Omron CX-Programmer project NewProject (CX-Programmer 7.20)

# PLC NewPLC1: CJ1M CPU11
I/O table (CPU CJ1M-CPU11): rack 0 slot 0 CJ1W-ETN21(ETN21Mode); rack 0 slot 1 CJ1W-ID211; rack 0 slot 2 CJ1W-OC211

## Program NewProgram1 (cyclic task 0)

### Section Section1

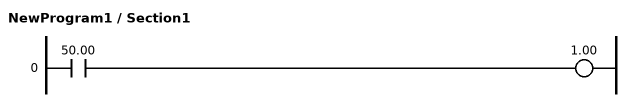
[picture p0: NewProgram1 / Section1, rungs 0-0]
; rung 0
LD 50.00
OUT 1.00

### Section END
; rung 0
END(001)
